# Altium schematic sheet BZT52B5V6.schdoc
size 127 x 101 mm
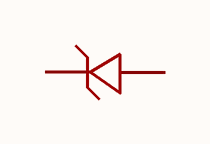
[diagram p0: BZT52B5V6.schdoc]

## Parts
D?  bzt52b5v6_c78578  [SOD-123_L2.8-W1.8-LS3.7-RD]  (value not drawn)

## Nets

Not connected (* = marked no-connect by the designer): D? 1(K) 2(A)

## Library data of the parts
D? = bzt52b5v6_c78578: 二极管配置:1个独立式;稳压值(标称值):5.6V;稳压值(范围):5.49V~5.71V;耗散功率(Pd):350mW;; Manufacturer: CJ(江苏长电/长晶); AddInBom: yes; ModelId: 7884390a25fb4c08947731ebfba7e3f8; ModelTransform: 144.8816,62.992,0,0,0,0,0,0,0; Diode Configuration: 1个独立式; Zener Voltage(Nom): 5.6V; Reverse Leakage Current (Ir): 1uA; Pd - Power Dissipation: 350mW; Impedance(Zzt): 40Ω; Impedance(Zzk): 400Ω; Operating Junction Temperature Range: -55℃~+150℃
